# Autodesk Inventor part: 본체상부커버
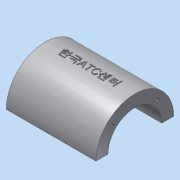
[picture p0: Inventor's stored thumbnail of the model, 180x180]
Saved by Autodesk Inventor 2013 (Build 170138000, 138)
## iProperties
Created: 2015-12
Part Number: 본체상부커버
Material: 알루미늄 6061
Document SubType Name: Modeling
Designer: mduedu
Density: 1 g/cm^3
Mass: 64.6353 g
Surface Area: 166.445 cm^2
Volume: 64.6353 cm^3
Author: mduedu
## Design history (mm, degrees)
sketch "스케치1"
  geometry: L1 (45, 40)-(-45, 40); L2 (-45, 40)-(-45, -40); L3 (-45, -40)-(45, -40); L4 (45, -40)-(45, 40); L5 (45, 40)-(-45, -40); L6 (-45, 40)-(45, -40); 2 further points
  constraints: 12 end point, 2 midpoint, 2 parallel, 1 coincident, 1 horizontal, 1 perpendicular, 3 other
  dimensions: "d0" = 90 distance of L2.end L3.end; "d2" = 80 distance of L1.end L2.end
extrude "돌출1" new body sketch "스케치1" distance "d3" = 10; taper "d4" = 0 deg
sketch "스케치2"
  geometry: C1 r 32.5 at (80, 0); 1 further point
  constraints: 1 centre point
  dimensions: "d5" = 65 diameter of C1; "d116" = 80 distance of point (0, 0) C1.centre
extrude "돌출2" join sketch "스케치2" stored distance "d7" = 75; taper "d8" = 0 deg
sketch "스케치3"
  geometry: L1 (-27.5, -20)-(27.5, -20); L2 (27.5, -20)-(27.5, 20); L3 (27.5, 20)-(-27.5, 20); L4 (-27.5, 20)-(-27.5, -20); L5 (-27.5, -20)-(27.5, 20); L6 (27.5, -20)-(-27.5, 20); 1 further point
  constraints: 12 end point, 2 midpoint, 2 parallel, 1 horizontal, 1 perpendicular
  dimensions: "d9" = 55 distance of L2.end L3.end; "d11" = 40 distance of L1.end L2.end
extrude "돌출3" new body sketch "스케치3" stored distance "d12" = 75; taper "d13" = 0 deg
fillet "모깎기1"
fillet "모깎기2"
feature "결합1"
  node "솔리드2"
sketch "스케치4"
  geometry: L1 (-37.5, 47.5)-(37.5, 47.5) reference; L2 (32.5, 47.5)-(40.208, 10); L3 (37.5, 47.5)-(37.5, 112.5) reference; L4 (60.208, 0)-(60.208, 10) reference; L5 (60.208, 10)-(-60.208, 10) reference; 1 further point
  constraints: 2 end point, 2 point on line
  dimensions: "d15" = 5 distance from line of L2.start L3; "d117" = 20 distance from line of L2.end L4
sketch "스케치5"
  geometry: L1 (10, 35.208)-(56.729, 22.687); L2 (0, 60.208)-(10, 60.208) reference; L3 (10, -60.208)-(10, 60.208) reference; 2 further points
  constraints: 2 end point, 1 point on line, 2 other
  dimensions: "d118" = 25 distance from line of L1.start L2; "d119" = 75 deg angle of L1 L3
feature "리브1" dims "d19" = 1, "d20" = 6, "d21" = 0, "d22" = 0, "d23" = 1, "d24" = 1
feature "리브2" dims "d25" = 1, "d26" = 6, "d27" = 0, "d28" = 0, "d29" = 1, "d30" = 1
fillet "모깎기4" dims "d31" = 2
fillet "모깎기5" dims "d32" = 2
fillet "모깎기6" dims "d33" = 2
sketch "스케치6"
  geometry: L1 (0, 0)-(-32.88, 32.88); L2 (0, 0)-(-46.5, 0); A1 r 46.5 centre (0, 0) between (-32.88, 32.88) and (-46.5, 0); 5 further points
  constraints: 4 end point, 2 coincident, 2 point on circle, 1 centre point, 1 horizontal, 5 other
  dimensions: "d120" = 93 diameter of A1; "d122" = 45 deg angle of L1 L2; "d126" = 360 deg dimension on point (0, 0) point (-32.88, 32.88) (derived)
hole "구멍1" sketch "스케치6" at (-32.88, 32.88), (-32.88, -32.88), (32.88, -32.88), (32.88, 32.88) diameter "d34" = 7; stored, may be unused: countersink angle "d38" = 90 deg, drill point angle "d40" = 118 deg; dims "d35" = 6, "d36" = 12, "d37" = 3, "d39" = 8
fillet "모깎기13" dims "d131" = 3
hole "구멍2" diameter "d44" = 45; stored, may be unused: countersink angle "d48" = 90 deg, drill point angle "d50" = 118 deg; dims "d42" = 10, "d43" = 10, "d45" = 6, "d46" = 4, "d47" = 2, "d49" = 8
sketch "스케치7" dims "d52" = 26.5
  geometry: L1 (0, 0)-(32.5, 0); L2 (0, 0)-(22.981, 22.981); A1 r 32.5 centre (0, 0) between (32.5, 0) and (22.981, 22.981) reference; 3 further points
  constraints: 4 end point, 2 point on circle, 1 coincident, 1 horizontal, 1 point on line, 3 other
  dimensions: "d51" = 45 deg angle of L2 L1
hole "구멍3" sketch "스케치7" at (18.738, 18.738) diameter "d54" = 2.459; stored, may be unused: countersink angle "d58" = 90 deg, drill point angle "d60" = 118 deg; dims "d55" = 8, "d56" = 4, "d57" = 2, "d59" = 10
sketch "스케치9"
  geometry: L1 (-75, -110)-(75, -110); L2 (75, -110)-(75, 0); L3 (75, 0)-(-75, 0); L4 (-75, 0)-(-75, -110); L5 (-60.208, -80)-(60.208, -80) reference; C1 r 32.5 at (0, 0) reference; 2 further points
  constraints: 8 end point, 2 parallel, 1 coincident, 1 horizontal, 1 midpoint, 1 perpendicular
  dimensions: "d148" = 30 distance between parallel lines of L5 L1; "d159" = 150 distance between parallel lines of L2 L4
extrude "돌출5" cut sketch "스케치9" stored distance "d73" = 0; taper "d74" = 0 deg
node "작업 평면3"
sketch "스케치17" dims "d2" = 80
  geometry: 2 further points
  constraints: 1 coincident, 1 other
feature "엠보싱1" sketch "스케치17" dims "d0" = 90, "d2" = 80, "d150" = 0.5, "d151" = 0
node "솔리드1"
mirror "대칭1"
mirror "대칭2"
pattern_circular "원형 패턴1" dims angle "d62" = 360 deg
mirror "대칭3"
